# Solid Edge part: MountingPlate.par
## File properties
Author: wojci
Template: ISO Metric Part.par
Last saved by: wojci
Revision: 7
Application: Solid Edge
Username: wojci
Accuracy: 0.990
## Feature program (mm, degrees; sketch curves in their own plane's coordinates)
sketch for "unnamed Protrusion 1" plane through (0, 0, 0) normal (0, -1, 0) x-axis (1, 0, 0)
  line (-25, 0) -> (25, 0)
  line (25, 0) -> (25, -10)
  line (25, -10) -> (60, -10)
  line (60, -10) -> (60, -20)
  line (60, -20) -> (-60, -20)
  line (-60, -20) -> (-60, -10)
  line (-60, -10) -> (-25, -10)
  line (-25, -10) -> (-25, 0)
extrude "unnamed Protrusion 1" add finite 50 symmetric
sketch for "ExtrudedProtrusion_2" plane through (0, 0, 0) normal (0, 0, 1) x-axis (0, 1, 0)
  line (13, 25) -> (13, -25)
  line (13, -25) -> (25, -25)
  line (25, -25) -> (25, 25)
  line (25, 25) -> (13, 25)
extrude "ExtrudedProtrusion_2" add finite 16 along +normal
sketch for "ExtrudedProtrusion_3" #1 plane through (0, 13, 7.5) normal (0, -1, 0) x-axis (1, 0, 0)
  circle centre (-13.5, 3.5) radius 2.0468
sketch for "ExtrudedProtrusion_3" #2 plane through (0, 13, 7.5) normal (0, -1, 0) x-axis (1, 0, 0)
  circle centre (13.5, 3.5) radius 2.0468
extrude "ExtrudedProtrusion_3" add finite 2.3 along +normal
sketch for "ExtrudedCutout_1" plane through (0, 19, 16) normal (0, 0, 1) x-axis (1, 0, 0)
  line (8, -6) -> (-8, -6)
  line (-8, -6) -> (-8, 6)
  line (-8, 6) -> (8, 6)
  line (8, 6) -> (8, -6)
extrude "ExtrudedCutout_1" cut finite 5 along -normal
sketch for "Hole_1" plane through (0, 19, 11) normal (0, 0, 1) x-axis (0, 1, 0)
  hole centre (-0.5, 0) bore radius 1.5
  dimension (linear) = 0.5
hole "Hole_1" diameter 3 finite
sketch for "Hole_2" plane through (13.5, 10.7, 10) normal (0, -1, 0) x-axis (1, 0, 0)
  hole centre (0, 1) bore radius 1.5
hole "Hole_2" diameter 3 finite
sketch for "unnamed Hole 1" plane through (13.5, 10.7, 10) normal (0, -1, 0) x-axis (1, 0, 0)
  hole centre (-27, 1) bore radius 1.5
hole "unnamed Hole 1" finite
sketch for "Hole_4" plane through (0, -6, 0) normal (0, 0, 1) x-axis (1, 0, 0)
hole "Hole_4" diameter 3 finite  ThreadDepth = 2 mm
sketch for "unnamed Hole 2" plane through (0, -6, 0) normal (0, 0, 1) x-axis (1, 0, 0)
hole "unnamed Hole 2" finite
fillet "unnamed Round 1"
sketch for "ExtrudedProtrusion_4" plane through (25, 0, 2.5) normal (1, 0, 0) x-axis (0, 1, 0)
  arc centre (14.2747, -17.4593) radius 20 from (1, -2.5) to (13, 2.5) cw
  line (13, -2.5) -> (13, 2.5)
  line (1, -2.5) -> (13, -2.5)
extrude "ExtrudedProtrusion_4" add finite 50 along -normal
pattern "unnamed Pattern 1" of "Hole_2", "unnamed Hole 1"
pattern "unnamed Pattern 2" of "Hole_4", "unnamed Hole 2"
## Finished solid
Body 1: solid body, 33 faces, 61 edges, 30 vertices.
  Faces by surface: plane 21, cylinder 12
  Edges by curve: line 39, circle 22
Bounding box of the edges (mm): 120.000 x 50.000 x 36.000, from (-60, -25, -20) to (60, 25, 16).
Cylindrical faces by radius (mm): R1.2295 x4, R1.5 x3, R2.0468 x2, R5 x2, R20 x1
Planar faces by outward normal: +x 2, +y 1, +z 9, -x 2, -y 6, -z 1
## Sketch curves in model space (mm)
line (25, 10.7, 11) -> (25, 25, 11)
line (25, -6, 0) -> (25, -6, -10)
line (25, 1, 0) -> (25, 1, -10)
line (25, 25, 5) -> (25, 13, 5)
line (25, 19, 16) -> (25, 19, -20)
line (25, 13, 0) -> (25, 13, 5)
line (25, 1, 0) -> (25, 13, 0)
arc centre (25, 14.2747, -14.9593) radius 20 from (25, 1, 0) through (25, 6.5824, 3.5022) to (25, 13, 5)
line (0, 25, 16) -> (0, 13, 16)
line (8, 25, 16) -> (8, 13, 16)
line (8, 13, 16) -> (-8, 13, 16)
line (-8, 13, 16) -> (-8, 25, 16)
line (-8, 25, 16) -> (8, 25, 16)
circle centre (13.5, 13, 11) radius 2.0468
circle centre (-13.5, 13, 11) radius 2.0468
line (-25, 13, 0) -> (25, 13, 0)
line (25, 13, 0) -> (25, 25, 0)
line (25, 25, 0) -> (-25, 25, 0)
line (-25, 25, 0) -> (-25, 13, 0)
line (25, 0, -20) -> (-25, 0, -20)
line (25, 0, 0) -> (25, 0, -10)
line (25, 0, -10) -> (60, 0, -10)
line (60, 0, -10) -> (60, 0, -20)
line (60, 0, -20) -> (-60, 0, -20)
line (-60, 0, -20) -> (-60, 0, -10)
line (-60, 0, -10) -> (-25, 0, -10)
line (-25, 0, -10) -> (-25, 0, 0)
line (-25, 0, 0) -> (25, 0, 0)
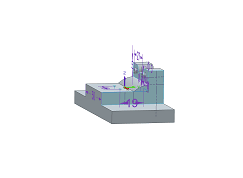
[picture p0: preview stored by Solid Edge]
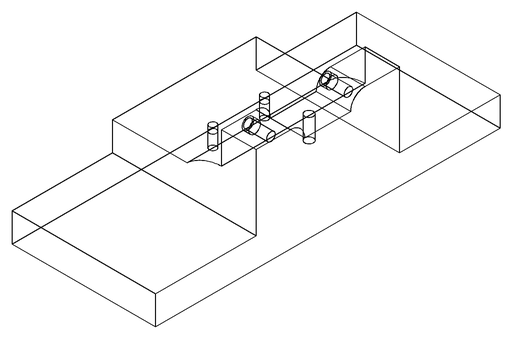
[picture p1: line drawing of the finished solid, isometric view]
